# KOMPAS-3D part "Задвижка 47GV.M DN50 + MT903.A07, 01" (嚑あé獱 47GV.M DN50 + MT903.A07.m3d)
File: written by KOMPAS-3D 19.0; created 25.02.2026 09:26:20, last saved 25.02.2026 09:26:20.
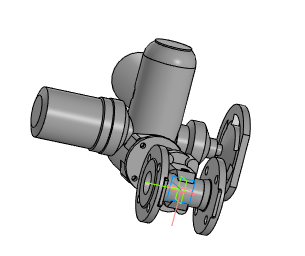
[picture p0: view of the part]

Document properties: Автор: Евгений; Полное имя файла: 47 GV.M DN50\Задвижка 47GV.M DN50 с переходом под ISO фланец.a3d

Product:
- Part/product: Задвижка 47GV.M DN50 + MT903.A07  | designation 01
    Масса: 10.055
  - Component [detail]: Удлинитель шпинделя  | Материал: Сталь 20Х13 ГОСТ 5632-72 (density 7670 kg/m3); Масса: 0.307911; source file: 47 GV.M DN50\DR.47GVAM.050.16.00.002 - Удлинитель шпинделя.cdw, 47 GV.M DN50\Удлинитель шпинделя DN50.m3d
  - Component [detail]: Стойка  | Материал: ВЧ50 ГОСТ 7293-85 (density 7200 kg/m3); Масса: 1.73762; Раздел спецификации: Детали; Форматы листов документа: 2xA3; source file: 47 GV.M DN50\DR.47GVAM.050.16.00.001 - Стойка.cdw, 47 GV.M DN50\Стойка DN50.m3d
  - Component [detail]: Корпус  | pos. 3  | Материал: ВЧ50 ГОСТ 7293-85 (density 7200 kg/m3); Масса: 8.77519; Раздел спецификации: Детали; Форматы листов документа: 2xA3; source file: 47 GV.M DN50\DR.47GVM.050.16.00.001 - Корпус.cdw, 47 GV.M DN50\Корпус 47GV.M DN50.m3d
  - Component [assembly]: Клин с направляющими  | designation DR.47GVM.050.16.01.000  | pos. 4  | Раздел спецификации: Сборочные единицы; Форматы листов документа: A4; source file: 47 GV.M DN50\DR.47GVM.050.16.01.000  - Клин с направляющими.a3d, 47 GV.M DN50\DR.47GVM.050.16.01.000  - Клин с направляющими.spw, 47 GV.M DN50\DR.47GVM.050.16.01.000  СБ - Клин с направляющими.cdw
  - Component [detail]: Крышка  | pos. 4  | Материал: ВЧ50 ГОСТ 7293-85 (density 7200 kg/m3); Масса: 2.87085; Раздел спецификации: Детали; source file: 47 GV.M DN50\DR.47GVM.050.16.00.002 - Крышка.cdw, 47 GV.M DN50\Крышка 47GV.M DN50.m3d
  - Component [detail]: Шпиндель  | pos. 5  | Материал: Сталь 20Х13 ГОСТ 5632-2014 (density 7670 kg/m3); Масса: 0.101759; Раздел спецификации: Детали; source file: 47 GV.M DN50\DR.47GVM.050.16.00.003 - Шпиндель.cdw, 47 GV.M DN50\Шпиндель 47GV.M DN50.m3d
  - Component: Электропривод МТ903.А07 без блока управления  | Масса: 65.4738; source file: 47 GV.M DN50\Электропривод МТ903.А07 без блока управления.m3d
- Part/product: Задвижка 47GV.M DN50 + MT903.A07
    Масса: 79.2782
    Раздел спецификации: Документация
    Форматы листов документа: 2xA3
  - Component: Задвижка с обрезиненным клином DN50. Сборочный чертеж  | designation DR.47GVM.050.16.00.000СБ  | pos. 0  | Масса: 10.0548; Раздел спецификации: Документация; Форматы листов документа: 2xA3; source file: 47 GV.M DN50\DR.47GVM.050.16.00.000 СБ - Задвижка с обрезиненным клином DN100.cdw

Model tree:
1. Операция без истории:1

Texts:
  Точка начала. Х
  Точка начала. Y
  Точка начала. Z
